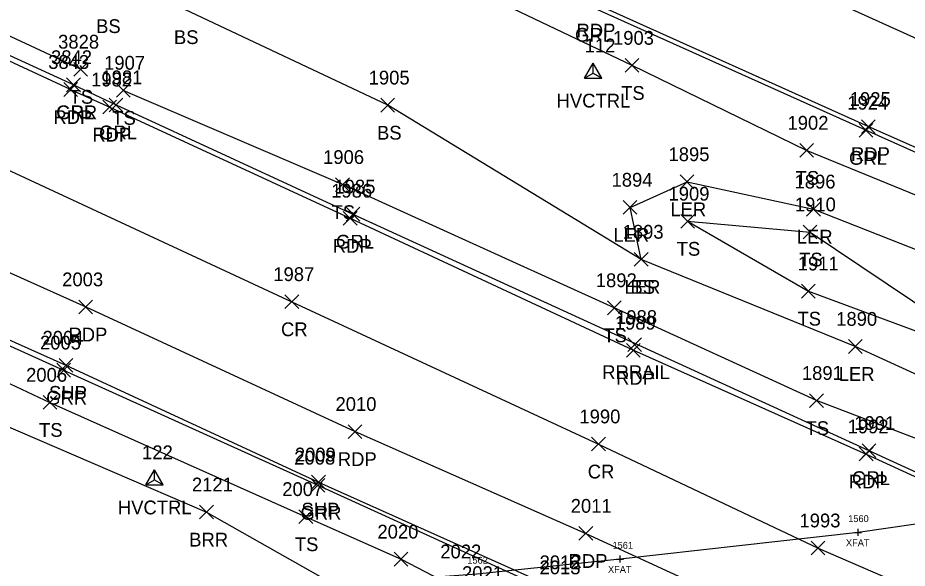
# Model space of a CAD drawing. Extents: x 1599569 to 1610055, y 642560 to 647860.
# Drawn here: x 1601388.5 to 1601517.7, y 647279.1 to 647359 of the extents above; entities that cross this region are included whole.
import ezdxf

# ---------------------------------------------------------------- set-up
doc = ezdxf.new("R2010")
doc.units = 0
for name, color, linetype in [('B_A', 7, 'Continuous'), ('B_I', 7, 'Continuous'), ('B_TIC', 7, 'Continuous'), ('BF', 7, 'Continuous'), ('C_A', 7, 'Continuous'), ('C_I', 7, 'Continuous'), ('CPSM', 7, 'Continuous'), ('L_A', 7, 'Continuous'), ('L_I', 7, 'Continuous'), ('L_TIC', 7, 'Continuous'), ('LABL', 7, 'Continuous'), ('LARO', 7, 'Continuous'), ('LELB', 7, 'Continuous'), ('P_A', 7, 'Continuous'), ('P_I', 7, 'Continuous'), ('P_TIC', 7, 'Continuous'), ('PET', 7, 'Continuous'), ('PRC', 7, 'Continuous'), ('PSP', 7, 'Continuous'), ('R_A', 7, 'Continuous'), ('R_I', 7, 'Continuous'), ('R_TIC', 7, 'Continuous'), ('RGR', 7, 'Continuous'), ('S_I', 7, 'Continuous')]:
    doc.layers.add(name, color=color, linetype=linetype)

msp = doc.modelspace()

# ---------------------------------------------------------------- linework, layer by layer
at = {"layer": 'B_TIC'}
for p, q in [((1601510.51, 647284.26), (1601510.59, 647284.26)), ((1601475.95, 647280.39), (1601476.02, 647280.39))]:
    msp.add_line(p, q, dxfattribs=at)
for points in [[(1601510.01, 647284.26), (1601511.01, 647284.26)], [(1601510.51, 647283.76), (1601510.51, 647284.76)], [(1601475.45, 647280.39), (1601476.45, 647280.39)], [(1601475.95, 647279.89), (1601475.95, 647280.89)]]:
    msp.add_lwpolyline(points, dxfattribs=at)
at = {"layer": 'BF'}
msp.add_lwpolyline([(1601746.01, 647335.35), (1601717.79, 647327.14), (1601692.8, 647320.35), (1601677.17, 647316.27), (1601645.45, 647308.52), (1601618.43, 647302.79), (1601602.8, 647299.49), (1601568.35, 647293.07), (1601543.36, 647288.97), (1601510.51, 647284.26), (1601475.95, 647280.39), (1601455.15, 647278.22), (1601422.22, 647275.79), (1601394.01, 647274.26), (1601380.77, 647273.7), (1601345.12, 647272.82), (1601321.94, 647272.73), (1601290.34, 647273.17)], dxfattribs=at)
at = {"layer": 'CPSM'}
for p, q in [((1601470.8, 647350.21), (1601472.05, 647352.38)), ((1601473.3, 647350.21), (1601472.05, 647352.38)), ((1601472.05, 647350.93), (1601472.05, 647352.38)), ((1601470.8, 647350.21), (1601472.05, 647350.93)), ((1601470.8, 647350.21), (1601473.3, 647350.21)), ((1601472.05, 647350.93), (1601472.05, 647350.93)), ((1601472.05, 647350.93), (1601473.3, 647350.21)), ((1601407.09, 647291.16), (1601408.34, 647293.33)), ((1601409.59, 647291.16), (1601408.34, 647293.33)), ((1601408.34, 647291.88), (1601408.34, 647293.33)), ((1601407.09, 647291.16), (1601408.34, 647291.88)), ((1601408.34, 647291.88), (1601408.34, 647291.88)), ((1601408.34, 647291.88), (1601409.59, 647291.16)), ((1601407.09, 647291.16), (1601409.59, 647291.16))]:
    msp.add_line(p, q, dxfattribs=at)
at = {"layer": 'L_TIC'}
for points in [[(1601396.61, 647350.48), (1601398.61, 647352.48)], [(1601398.61, 647350.48), (1601396.61, 647352.48)], [(1601476.7, 647351.04), (1601478.7, 647353.04)], [(1601478.7, 647351.04), (1601476.7, 647353.04)], [(1601402.81, 647347.42), (1601404.81, 647349.42)], [(1601404.81, 647347.42), (1601402.81, 647349.42)], [(1601441.22, 647345.27), (1601443.22, 647347.27)], [(1601443.22, 647345.27), (1601441.22, 647347.27)], [(1601502.04, 647338.71), (1601504.04, 647340.71)], [(1601504.04, 647338.71), (1601502.04, 647340.71)], [(1601434.65, 647333.74), (1601436.65, 647335.74)], [(1601436.65, 647333.74), (1601434.65, 647335.74)], [(1601484.68, 647334.15), (1601486.68, 647336.15)], [(1601486.68, 647334.15), (1601484.68, 647336.15)], [(1601476.41, 647330.44), (1601478.41, 647332.44)], [(1601478.41, 647330.44), (1601476.41, 647332.44)], [(1601503.04, 647330.18), (1601505.04, 647332.18)], [(1601505.04, 647330.18), (1601503.04, 647332.18)], [(1601484.77, 647328.42), (1601486.77, 647330.42)], [(1601486.77, 647328.42), (1601484.77, 647330.42)], [(1601484.77, 647328.42), (1601486.77, 647330.42)], [(1601486.77, 647328.42), (1601484.77, 647330.42)], [(1601502.55, 647326.86), (1601504.55, 647328.86)], [(1601504.55, 647326.86), (1601502.55, 647328.86)], [(1601478.02, 647322.89), (1601480.02, 647324.89)], [(1601480.02, 647322.89), (1601478.02, 647324.89)], [(1601478.02, 647322.89), (1601480.02, 647324.89)], [(1601480.02, 647322.89), (1601478.02, 647324.89)], [(1601502.31, 647318.28), (1601504.31, 647320.28)], [(1601504.31, 647318.28), (1601502.31, 647320.28)], [(1601474.12, 647315.86), (1601476.12, 647317.86)], [(1601476.12, 647315.86), (1601474.12, 647317.86)], [(1601509.12, 647310.25), (1601511.12, 647312.25)], [(1601511.12, 647310.25), (1601509.12, 647312.25)], [(1601392.17, 647302.13), (1601394.17, 647304.13)], [(1601394.17, 647302.13), (1601392.17, 647304.13)], [(1601503.48, 647302.39), (1601505.48, 647304.39)], [(1601505.48, 647302.39), (1601503.48, 647304.39)], [(1601414.9, 647286.21), (1601416.9, 647288.21)], [(1601416.9, 647286.21), (1601414.9, 647288.21)], [(1601429.32, 647285.54), (1601431.32, 647287.54)], [(1601431.32, 647285.54), (1601429.32, 647287.54)], [(1601443.15, 647279.37), (1601445.15, 647281.37)], [(1601445.15, 647279.37), (1601443.15, 647281.37)]]:
    msp.add_lwpolyline(points, dxfattribs=at)
at = {"layer": 'LABL'}
msp.add_lwpolyline([(1601168.99, 647399.27), (1601207.41, 647380.73), (1601257.17, 647358.28), (1601294.19, 647341.7), (1601346.91, 647319.14), (1601374.73, 647304.92), (1601415.9, 647287.21), (1601447.46, 647269.36), (1601451.82, 647260.74), (1601445.32, 647247.33), (1601438.38, 647230.38)], dxfattribs=at)
at = {"layer": 'LARO'}
msp.add_lwpolyline([(1601562.62, 647287.1), (1601538.24, 647298.37), (1601510.12, 647311.25), (1601479.02, 647323.89), (1601477.41, 647331.44), (1601485.68, 647335.15), (1601504.04, 647331.18), (1601538.23, 647317.74)], dxfattribs=at)
at = {"layer": 'LELB'}
for points in [[(1601397.61, 647351.48), (1601365.05, 647366.71), (1601330.24, 647382.11), (1601297.6, 647397.08), (1601270.69, 647410.14), (1601258.21, 647415.18)], [(1601601.89, 647296.79), (1601570.79, 647311.1), (1601534.14, 647326.95), (1601503.04, 647339.71), (1601477.7, 647352.04), (1601450.37, 647365.08)], [(1601479.02, 647323.89), (1601442.22, 647346.27), (1601412.73, 647360.14)], [(1601535.76, 647291.45), (1601504.48, 647303.39), (1601475.12, 647316.86), (1601435.65, 647334.74), (1601403.81, 647348.42)], [(1601312.72, 647340.63), (1601348.67, 647324.04), (1601393.17, 647303.13), (1601430.32, 647286.54), (1601444.15, 647280.37), (1601455.78, 647274.35)], [(1601485.77, 647329.42), (1601503.55, 647327.86), (1601522.12, 647315.42), (1601541.29, 647312.23), (1601564.39, 647299.9)], [(1601485.77, 647329.42), (1601503.31, 647319.28), (1601521.09, 647312.7), (1601547.3, 647300.47), (1601561.12, 647295.15), (1601564.39, 647299.9)]]:
    msp.add_lwpolyline(points, dxfattribs=at)
at = {"layer": 'P_TIC'}
for points in [[(1601395.17, 647347.54), (1601397.17, 647349.54)], [(1601397.17, 647347.54), (1601395.17, 647349.54)], [(1601400.84, 647344.99), (1601402.84, 647346.99)], [(1601402.84, 647344.99), (1601400.84, 647346.99)], [(1601511, 647342.16), (1601513, 647344.16)], [(1601513, 647342.16), (1601511, 647344.16)], [(1601435.76, 647328.85), (1601437.76, 647330.85)], [(1601437.76, 647328.85), (1601435.76, 647330.85)], [(1601397.36, 647315.98), (1601399.36, 647317.98)], [(1601399.36, 647315.98), (1601397.36, 647317.98)], [(1601427.29, 647316.74), (1601429.29, 647318.74)], [(1601429.29, 647316.74), (1601427.29, 647318.74)], [(1601476.89, 647309.69), (1601478.89, 647311.69)], [(1601478.89, 647309.69), (1601476.89, 647311.69)], [(1601394.49, 647307.51), (1601396.49, 647309.51)], [(1601396.49, 647307.51), (1601394.49, 647309.51)], [(1601436.48, 647297.89), (1601438.48, 647299.89)], [(1601438.48, 647297.89), (1601436.48, 647299.89)], [(1601471.83, 647296.09), (1601473.83, 647298.09)], [(1601473.83, 647296.09), (1601471.83, 647298.09)], [(1601510.69, 647294.64), (1601512.69, 647296.64)], [(1601512.69, 647294.64), (1601510.69, 647296.64)], [(1601431.16, 647290.56), (1601433.16, 647292.56)], [(1601433.16, 647290.56), (1601431.16, 647292.56)], [(1601469.99, 647283.11), (1601471.99, 647285.11)], [(1601471.99, 647283.11), (1601469.99, 647285.11)], [(1601503.71, 647280.99), (1601505.71, 647282.99)], [(1601505.71, 647280.99), (1601503.71, 647282.99)]]:
    msp.add_lwpolyline(points, dxfattribs=at)
at = {"layer": 'PET'}
for points in [[(1601396.17, 647348.54), (1601351.62, 647369.26), (1601306.84, 647389.58), (1601254.97, 647413.31)], [(1601973.38, 647134.15), (1601930.79, 647153.54), (1601888.64, 647172.44), (1601843.17, 647192.94), (1601801.06, 647212.25), (1601760.52, 647230.65), (1601718.64, 647249.66), (1601675.39, 647269.62), (1601633.17, 647289.14), (1601607.86, 647300.47), (1601588.56, 647309.14), (1601555.09, 647324.12), (1601512, 647343.16), (1601472.14, 647361.1), (1601457.8, 647367.35)], [(1601396.17, 647348.54), (1601401.84, 647345.99)], [(1601331.98, 647346.68), (1601356.59, 647335.73), (1601398.36, 647316.98), (1601437.48, 647298.89), (1601470.99, 647284.11), (1601510.02, 647266.15), (1601543.75, 647251.34), (1601580.52, 647234.21), (1601606.39, 647222.8), (1601650.31, 647202.92), (1601693.14, 647183.7), (1601742.76, 647160.97), (1601795.46, 647137.6), (1601852.51, 647112.19)], [(1601401.84, 647345.99), (1601436.76, 647329.85), (1601477.89, 647310.69), (1601511.69, 647295.64), (1601529.2, 647287.58), (1601568.21, 647270.13), (1601613.57, 647249.46), (1601666.31, 647226.36), (1601709.07, 647207.41), (1601751.08, 647188.42), (1601796.47, 647168.32), (1601839.63, 647148.76), (1601881.89, 647129.58), (1601912.89, 647115.63)]]:
    msp.add_lwpolyline(points, dxfattribs=at)
at = {"layer": 'PRC'}
for points in [[(1602004.91, 647136.4), (1601979.09, 647147.72), (1601938.18, 647166.06), (1601894.66, 647185.48), (1601851.67, 647205.52), (1601807.6, 647224.86), (1601766.29, 647241.91), (1601725.38, 647262.23), (1601683.79, 647281.85), (1601638.16, 647302.69), (1601616.13, 647312.82), (1601597.54, 647321.11), (1601562.74, 647336.75), (1601520.64, 647355.15), (1601479.31, 647373.89)], [(1601345.39, 647355.71), (1601383.98, 647338.31), (1601428.29, 647317.74), (1601472.83, 647297.09), (1601504.71, 647281.99), (1601534.71, 647269.01), (1601561.28, 647257.19), (1601605.65, 647237.34), (1601658.4, 647213.63), (1601702.28, 647194), (1601743.84, 647175.46), (1601792.12, 647154.22), (1601833.09, 647135.23), (1601874.76, 647116.71)]]:
    msp.add_lwpolyline(points, dxfattribs=at)
at = {"layer": 'PSP'}
msp.add_lwpolyline([(1601320.4, 647342.24), (1601352.25, 647327.85), (1601395.49, 647308.51), (1601432.16, 647291.56), (1601467.04, 647275.92), (1601506.79, 647257.96), (1601540.92, 647242.41), (1601577, 647226.25), (1601607.65, 647212.12), (1601646.7, 647194.68), (1601690.56, 647174.95), (1601738.15, 647153.57), (1601769.56, 647138.92), (1601808.48, 647121.32)], dxfattribs=at)
at = {"layer": 'R_TIC'}
for points in [[(1601395.58, 647348.23), (1601397.58, 647350.23)], [(1601397.58, 647348.23), (1601395.58, 647350.23)], [(1601395.58, 647348.23), (1601397.58, 647350.23)], [(1601397.58, 647348.23), (1601395.58, 647350.23)], [(1601401.77, 647345.31), (1601403.77, 647347.31)], [(1601403.77, 647345.31), (1601401.77, 647347.31)], [(1601510.66, 647341.62), (1601512.66, 647343.62)], [(1601512.66, 647341.62), (1601510.66, 647343.62)], [(1601436.17, 647329.45), (1601438.17, 647331.45)], [(1601438.17, 647329.45), (1601436.17, 647331.45)], [(1601477.08, 647310.51), (1601479.08, 647312.51)], [(1601479.08, 647310.51), (1601477.08, 647312.51)], [(1601394.14, 647306.81), (1601396.14, 647308.81)], [(1601396.14, 647306.81), (1601394.14, 647308.81)], [(1601511.1, 647295.13), (1601513.1, 647297.13)], [(1601513.1, 647295.13), (1601511.1, 647297.13)], [(1601431.06, 647290.1), (1601433.06, 647292.1)], [(1601433.06, 647290.1), (1601431.06, 647292.1)]]:
    msp.add_lwpolyline(points, dxfattribs=at)
at = {"layer": 'RGR'}
for points in [[(1601396.58, 647349.23), (1601351.85, 647369.72), (1601307.17, 647390.02), (1601255.19, 647413.85)], [(1601973.06, 647133.72), (1601930.49, 647152.82), (1601887.99, 647171.84), (1601842.93, 647192.4), (1601800.73, 647211.54), (1601759.97, 647229.98), (1601718.53, 647248.97), (1601675.12, 647269.02), (1601632.93, 647288.53), (1601607.5, 647300), (1601588.34, 647308.52), (1601554.72, 647323.41), (1601511.66, 647342.62), (1601471.88, 647360.48), (1601457.01, 647367.11)], [(1601396.58, 647349.23), (1601402.77, 647346.31)], [(1601402.77, 647346.31), (1601437.17, 647330.45), (1601512.1, 647296.13), (1601530.55, 647287.7), (1601568.72, 647270.81), (1601614.15, 647250.08), (1601638.3, 647239.5)], [(1601318.76, 647342.22), (1601351.89, 647327.35), (1601395.14, 647307.81), (1601432.06, 647291.1), (1601467.03, 647275.18), (1601506.65, 647256.87), (1601540.97, 647241.89), (1601576.91, 647225.43), (1601607.45, 647211.71), (1601646.25, 647193.96), (1601690.44, 647174.37), (1601737.84, 647152.88), (1601768.28, 647138.94), (1601807.48, 647120.85)]]:
    msp.add_lwpolyline(points, dxfattribs=at)

# ---------------------------------------------------------------- texts
at = {"layer": 'B_A'}
for p in [(1601508.76, 647282.26), (1601474.2, 647278.39)]:
    msp.add_text('XFAT', height=1, dxfattribs=at).set_placement(p)
at = {"layer": 'B_I'}
for s, p in [('1560', (1601509.09, 647285.76)), ('1561', (1601474.86, 647281.89)), ('1562', (1601453.78, 647279.72))]:
    msp.add_text(s, height=1, dxfattribs=at).set_placement(p)
at = {"layer": 'C_A'}
for p in [(1601466.74, 647345.93), (1601403.03, 647286.88)]:
    msp.add_text('HVCTRL', height=2, dxfattribs=at).set_placement(p)
at = {"layer": 'C_I'}
for s, p in [('112', (1601470.82, 647353.93)), ('122', (1601406.54, 647294.88))]:
    msp.add_text(s, height=2, dxfattribs=at).set_placement(p)
at = {"layer": 'L_A'}
for s, p in [('BS', (1601399.87, 647356.74)), ('BS', (1601411.17, 647355.14)), ('TS', (1601476.11, 647347.04)), ('TS', (1601396.02, 647346.48)), ('TS', (1601402.21, 647343.42)), ('BS', (1601440.66, 647341.27)), ('TS', (1601501.45, 647334.71)), ('TS', (1601434.06, 647329.74)), ('LER', (1601483.26, 647330.15)), ('LER', (1601474.99, 647326.44)), ('LER', (1601501.62, 647326.18)), ('TS', (1601484.18, 647324.42)), ('TS', (1601484.18, 647324.42)), ('TS', (1601501.96, 647322.86)), ('LER', (1601476.61, 647318.89)), ('BS', (1601477.47, 647318.89)), ('TS', (1601501.72, 647314.28)), ('TS', (1601473.53, 647311.86)), ('LER', (1601507.71, 647306.25)), ('TS', (1601391.58, 647298.13)), ('TS', (1601502.89, 647298.39)), ('BRR', (1601413.39, 647282.21)), ('TS', (1601428.73, 647281.54))]:
    msp.add_text(s, height=2, dxfattribs=at).set_placement(p)
at = {"layer": 'L_I'}
for s, p in [('3828', (1601394.35, 647354.48)), ('1903', (1601474.93, 647355.04)), ('1907', (1601401.03, 647351.42)), ('1905', (1601439.45, 647349.27)), ('1902', (1601500.27, 647342.71)), ('1906', (1601432.83, 647337.74)), ('1895', (1601482.99, 647338.15)), ('1894', (1601474.72, 647334.44)), ('1896', (1601501.29, 647334.18)), ('1909', (1601482.99, 647332.42)), ('1909', (1601482.99, 647332.42)), ('1910', (1601501.34, 647330.86)), ('1893', (1601476.33, 647326.89)), ('1893', (1601476.33, 647326.89)), ('1911', (1601501.76, 647322.28)), ('1892', (1601472.43, 647319.86)), ('1890', (1601507.34, 647314.25)), ('2006', (1601389.7, 647306.13)), ('1891', (1601502.36, 647306.39)), ('2121', (1601413.78, 647290.21)), ('2007', (1601426.9, 647289.54)), ('2020', (1601440.72, 647283.37)), ('2021', (1601453.01, 647277.35))]:
    msp.add_text(s, height=2, dxfattribs=at).set_placement(p)
at = {"layer": 'P_A'}
for s, p in [('RDP', (1601469.63, 647356.1)), ('RDP', (1601393.66, 647343.54)), ('RDP', (1601399.32, 647340.99)), ('RDP', (1601509.49, 647338.16)), ('RDP', (1601434.25, 647324.85)), ('RDP', (1601395.85, 647311.98)), ('CR', (1601426.72, 647312.74)), ('RDP', (1601475.38, 647305.69)), ('SHP', (1601393.03, 647303.51)), ('RDP', (1601434.97, 647293.89)), ('CR', (1601471.26, 647292.09)), ('RDP', (1601509.18, 647290.64)), ('SHP', (1601429.69, 647286.56)), ('RDP', (1601468.48, 647279.11))]:
    msp.add_text(s, height=2, dxfattribs=at).set_placement(p)
at = {"layer": 'P_I'}
for s, p in [('3843', (1601392.91, 647351.54)), ('1982', (1601399.14, 647348.99)), ('1925', (1601509.31, 647346.16)), ('1986', (1601434.01, 647332.85)), ('1987', (1601425.6, 647320.74)), ('2003', (1601394.94, 647319.98)), ('1989', (1601475.19, 647313.69)), ('2004', (1601392.08, 647311.51)), ('2010', (1601434.63, 647301.89)), ('1990', (1601470.05, 647300.09)), ('1992', (1601509, 647298.64)), ('2009', (1601428.73, 647294.56)), ('2011', (1601468.79, 647287.11)), ('1993', (1601502.01, 647284.99)), ('2012', (1601464.26, 647278.92))]:
    msp.add_text(s, height=2, dxfattribs=at).set_placement(p)
at = {"layer": 'R_A'}
for s, p in [('GRL', (1601469.42, 647355.48)), ('GRR', (1601394.07, 647344.23)), ('GRL', (1601394.12, 647344.23)), ('GRL', (1601400.31, 647341.31)), ('GRL', (1601509.2, 647337.62)), ('GRL', (1601434.71, 647325.45)), ('RRRAIL', (1601473.37, 647306.51)), ('GRR', (1601392.62, 647302.81)), ('GRL', (1601509.64, 647291.13)), ('GRR', (1601429.55, 647286.1))]:
    msp.add_text(s, height=2, dxfattribs=at).set_placement(p)
at = {"layer": 'R_I'}
for s, p in [('3842', (1601393.32, 647352.23)), ('3842', (1601393.32, 647352.23)), ('1981', (1601400.64, 647349.31)), ('1924', (1601508.96, 647345.62)), ('1985', (1601434.48, 647333.45)), ('1988', (1601475.38, 647314.51)), ('2005', (1601391.72, 647310.81)), ('1991', (1601509.97, 647299.13)), ('2008', (1601428.64, 647294.1)), ('2013', (1601464.26, 647278.18))]:
    msp.add_text(s, height=2, dxfattribs=at).set_placement(p)
at = {"layer": 'S_I'}
msp.add_text('2022', height=2, dxfattribs=at).set_placement((1601449.85, 647280.49))

doc.saveas('drawing.dxf')
